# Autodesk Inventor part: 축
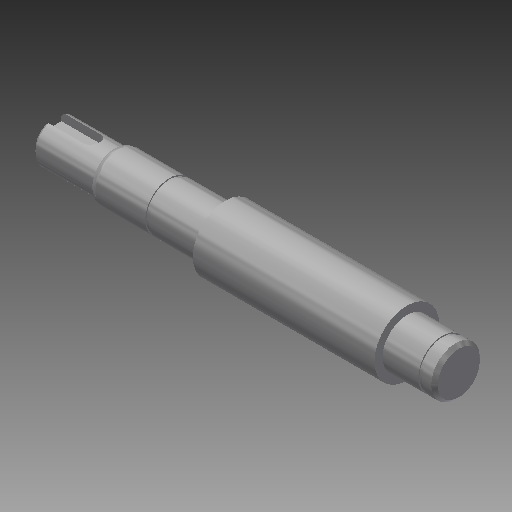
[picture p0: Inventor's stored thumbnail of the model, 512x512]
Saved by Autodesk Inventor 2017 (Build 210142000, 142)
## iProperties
Created: 2015-12
Part Number: 축
Material: 강철, 연강
Document SubType Name: Modeling
Designer: mduedu
Density: 7.86 g/cm^3
Appearance: 강철
Author: mduedu
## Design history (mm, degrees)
sketch "스케치1"
  geometry: L1 (-62.5, 0)-(62.5, 0); L2 (-62.5, 0)-(-62.5, 6.5); L3 (-62.5, 6.5)-(-43.5, 6.5); L4 (-43.5, 7)-(-42.634, 7.5); L5 (-42.634, 7.5)-(-9.5, 7.5); L6 (-9.5, 7.5)-(-9.5, 10); L7 (-9.5, 10)-(46.5, 10); L8 (46.5, 10)-(46.5, 7.5); L9 (46.5, 7.5)-(62.5, 7.5); L10 (62.5, 7.5)-(62.5, 0); L11 (-43.5, 6.5)-(-43.5, 7); 2 further points
  constraints: 22 end point, 6 parallel, 2 perpendicular, 1 coincident, 1 horizontal, 1 midpoint, 1 vertical
  dimensions: "d0" = 13 diameter of L3 L1; "d2" = 15 diameter of L5 L1; "d3" = 20 diameter of L7 L1; "d5" = 15 diameter of L9 L1; "d6" = 125 distance of L1.start L1.end; "d7" = 19 distance of L2.end L3.end; "d8" = 34 distance from line of L6 L3.end; "d9" = 56 distance of L6.end L7.end; "d41" = 14 diameter of L4.start L1; "d42" = 30 deg angle of L4 L3
revolve "회전1" sketch "스케치1" stored, may be unused: angle "d11" = 90 deg
node "작업 평면1"
node "작업 평면2"
sketch "스케치3"
  geometry: L1 (9.5, -2.5)-(-2.5, -2.5); L2 (-2.5, 2.5)-(9.5, 2.5); L3 (9.5, 2.5)-(9.5, -2.5); L4 (9.5, 6.5)-(9.5, -6.5) reference; A1 r 2.5 centre (-2.5, 0) between (-2.5, 2.5) and (-2.5, -2.5); 1 further point
  constraints: 6 end point, 2 point on circle, 2 tangent, 1 centre point, 1 collinear, 1 horizontal, 1 horizontal alignment, 1 parallel
  dimensions: "d17" = 5 distance of L2.end L1.start; "d19" = 12 distance from line of A1.centre L3
extrude "돌출2" cut sketch "스케치3" distance "d20" = 3; taper "d21" = 0 deg
chamfer "모따기1" distance "d22" = 1; stored, may be unused: second distance "d23" = 2, angle "d24" = 45 deg
fillet "모깎기1" dims "d25" = 3
sketch "스케치4"
  geometry: L1 (-9.5, -10)-(-9.5, 10) reference; L2 (-9.5, 0)-(0, 0); L3 (-26.65, 12.15)-(-25.5, 12.15); L4 (-25.5, 12.15)-(-25.5, 7.15); L5 (-25.5, 7.15)-(-26.65, 7.15); L6 (-26.65, 7.15)-(-26.65, 12.15); L7 (57.5, 12.15)-(58.65, 12.15); L8 (58.65, 12.15)-(58.65, 7.15); L9 (58.65, 7.15)-(57.5, 7.15); L10 (57.5, 7.15)-(57.5, 12.15); L11 (62.5, -7.5)-(62.5, 7.5) reference
  constraints: 18 end point, 4 parallel, 2 horizontal, 2 perpendicular, 1 midpoint
  dimensions: "d26" = 16 distance between parallel lines of L4 L1; "d27" = 1.15 distance of L3.start L3.end; "d28" = 14.3 diameter of L5 L2; "d29" = 5 distance of L3.end L4.end; "d30" = 1.15 distance of L7.start L7.end; "d31" = 5 distance of L7.end L8.end; "d32" = 5 distance between parallel lines of L10 L11; "d33" = 14.3 diameter of L9 L2
revolve "회전2" sketch "스케치4" stored, may be unused: angle "d34" = 90 deg
chamfer "모따기2" distance "d35" = 1; stored, may be unused: second distance "d36" = 2, angle "d37" = 45 deg
sketch "스케치5"
  geometry: 2 further points
  constraints: 1 coincident
sketch "스케치6"
  geometry: 1 further point
hole "구멍1" sketch "스케치6" at (2.5, -3.5) diameter "d43" = 4.917; stored, may be unused: countersink angle "d47" = 90 deg, drill point angle "d49" = 120 deg; dims "d44" = 14, "d45" = 4, "d46" = 2, "d48" = 17
node "솔리드1"
other parameters: "d12" = -15.5
